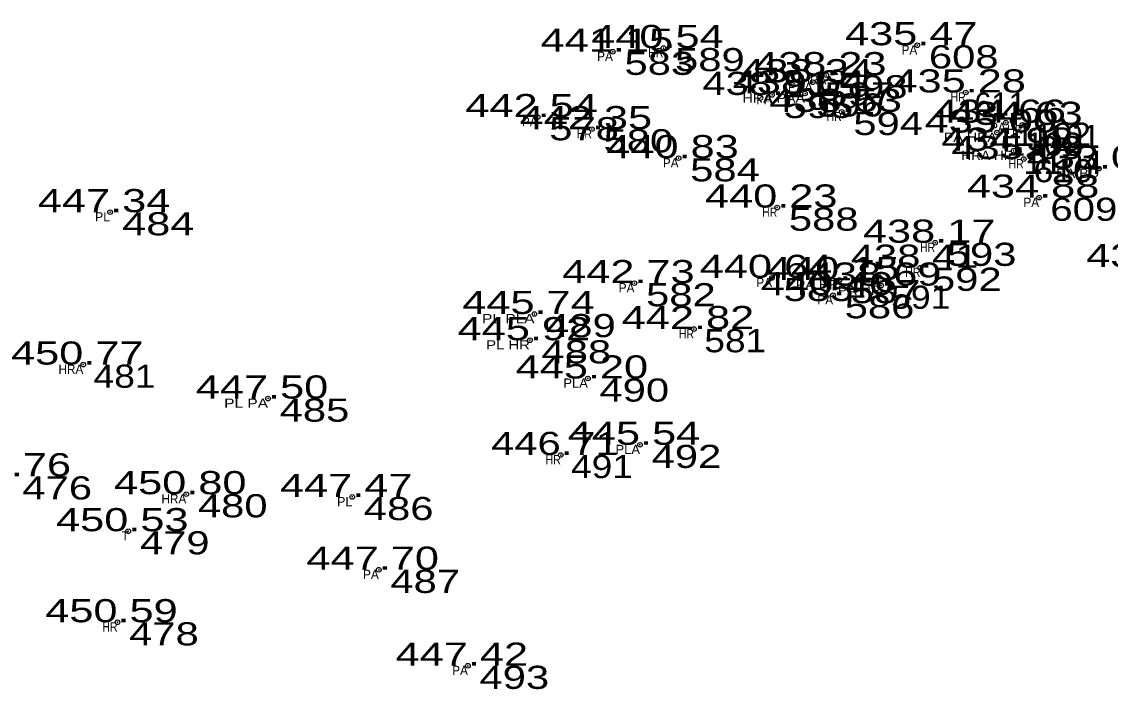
# Model space of a CAD drawing. Extents: x -639390 to -639074, y -1138747 to -1138358.
# Drawn here: x -639129.77 to -639094.48, y -1138747.34 to -1138725.71 of the extents above; entities that cross this region are included whole.
import ezdxf
from ezdxf.enums import TextEntityAlignment as Align

# ---------------------------------------------------------------- set-up
doc = ezdxf.new("R2010")
doc.units = 0
doc.header["$LTSCALE"] = 0.3
doc.header["$PDMODE"] = 32
doc.header["$PDSIZE"] = 0.15
for name, color, linetype in [('11', 7, 'Continuous'), ('12', 7, 'Continuous'), ('13', 7, 'Continuous'), ('57', 7, 'Continuous')]:
    doc.layers.add(name, color=color, linetype=linetype)

msp = doc.modelspace()

# ---------------------------------------------------------------- linework, layer by layer
at = {"layer": '11'}
for p in [(-639100.74, -1138726.47), (-639110.61, -1138726.68), (-639108.97, -1138726.56), (-639103.69, -1138727.44), (-639104.13, -1138727.67), (-639105.45, -1138728.08), (-639104.38, -1138728.03), (-639099.17, -1138728), (-639113.05, -1138728.8), (-639103.19, -1138728.63), (-639111.29, -1138729.19), (-639097.87, -1138728.98), (-639097.33, -1138729.05), (-639098.16, -1138729.3), (-639097.62, -1138729.89), (-639108.48, -1138730.13), (-639097.29, -1138730.16), (-639094.85, -1138730.47), (-639096.79, -1138731.41), (-639105.28, -1138731.73), (-639126.91, -1138731.88), (-639100.16, -1138732.87), (-639100.64, -1138733.68), (-639109.91, -1138734.18), (-639105.45, -1138734.01), (-639103.27, -1138734.08), (-639103.47, -1138734.57), (-639101.91, -1138734.26), (-639113.15, -1138735.18), (-639107.98, -1138735.67), (-639113.3, -1138736.03), (-639127.78, -1138736.82), (-639111.42, -1138737.27), (-639121.79, -1138737.92), (-639109.73, -1138739.42), (-639112.3, -1138739.75), (-639124.44, -1138741.02), (-639119.06, -1138741.11), (-639126.32, -1138742.22), (-639118.2, -1138743.47), (-639126.67, -1138745.17), (-639115.31, -1138746.58)]:
    msp.add_point(p, dxfattribs=at)

# ---------------------------------------------------------------- texts
at = {"layer": '12'}
for s, width, p in [('441.15 ', 1.4, (-639110.61, -1138726.68)), ('440.54 ', 1.4, (-639108.97, -1138726.56)), ('435.47 ', 1.4, (-639100.74, -1138726.47)), ('438.23 ', 1.4, (-639103.69, -1138727.44)), ('438.34 ', 1.4, (-639104.13, -1138727.67)), ('438.91 ', 1.35, (-639105.449, -1138728.08)), ('438.64 ', 1.4, (-639104.38, -1138728.03)), ('435.28 ', 1.4, (-639099.17, -1138728)), ('442.54 ', 1.4, (-639113.05, -1138728.8)), ('438.53 ', 1.4, (-639103.19, -1138728.63)), ('442.35 ', 1.4, (-639111.29, -1138729.19)), ('434.66 ', 1.4, (-639097.869, -1138728.98)), ('434.63 ', 1.4, (-639097.33, -1138729.05)), ('435.00 ', 1.4, (-639098.16, -1138729.3)), ('434.98 ', 1.4, (-639097.62, -1138729.89)), ('440.83 ', 1.4, (-639108.48, -1138730.13)), ('435.09 ', 1.4, (-639097.29, -1138730.16)), ('433.09 ', 1.4, (-639094.85, -1138730.47)), ('440.23 ', 1.4, (-639105.28, -1138731.73)), ('434.88 ', 1.4, (-639096.79, -1138731.41)), ('447.34 ', 1.4, (-639126.91, -1138731.88)), ('438.17 ', 1.4, (-639100.16, -1138732.87)), ('438.41 ', 1.35, (-639100.639, -1138733.68)), ('434.18 ', 1.4, (-639092.92, -1138733.66)), ('442.73 ', 1.4, (-639109.91, -1138734.18)), ('440.64 ', 1.4, (-639105.45, -1138734.01)), ('440.15 ', 1.4, (-639103.27, -1138734.08)), ('440.40 ', 1.4, (-639103.47, -1138734.57)), ('438.69 ', 1.4, (-639101.91, -1138734.26)), ('445.74 ', 1.4, (-639113.15, -1138735.18)), ('442.82 ', 1.4, (-639107.98, -1138735.67)), ('445.92 ', 1.4, (-639113.3, -1138736.03)), ('450.77 ', 1.4, (-639127.78, -1138736.82)), ('445.20 ', 1.4, (-639111.42, -1138737.27)), ('447.50 ', 1.4, (-639121.79, -1138737.92)), ('445.54 ', 1.4, (-639109.73, -1138739.42)), ('446.71 ', 1.35, (-639112.299, -1138739.75)), ('450.76 ', 1.4, (-639130.129, -1138740.44)), ('450.80 ', 1.4, (-639124.44, -1138741.02)), ('447.47 ', 1.4, (-639119.06, -1138741.11)), ('450.53 ', 1.4, (-639126.32, -1138742.22)), ('447.70 ', 1.4, (-639118.2, -1138743.47)), ('450.59 ', 1.4, (-639126.67, -1138745.17)), ('447.42 ', 1.4, (-639115.31, -1138746.58))]:
    msp.add_text(s, height=0.75, dxfattribs=dict(at, width=width)).set_placement(p, align=Align.CENTER)
at = {"layer": '13'}
for s, width, p in [(' 583', 1.35, (-639110.61, -1138727.43)), (' 589', 1.35, (-639108.97, -1138727.31)), (' 608', 1.35, (-639100.74, -1138727.22)), (' 598', 1.35, (-639103.69, -1138728.19)), (' 597', 1.35, (-639104.13, -1138728.42)), (' 595', 1.35, (-639105.45, -1138728.83)), (' 596', 1.3, (-639104.38, -1138728.78)), (' 578', 1.35, (-639113.05, -1138729.55)), (' 594', 1.35, (-639103.19, -1138729.38)), (' 580', 1.35, (-639111.29, -1138729.94)), (' 1102', 1.1, (-639097.87, -1138729.73)), (' 1103', 1.1, (-639098.16, -1138730.05)), (' 1104', 1.15, (-639097.62, -1138730.64)), (' 584', 1.35, (-639108.48, -1138730.88)), (' 610', 1.15, (-639097.29, -1138730.91)), (' 609', 1.3, (-639096.79, -1138732.16)), (' 484', 1.4, (-639126.91, -1138732.63)), (' 588', 1.35, (-639105.28, -1138732.48)), (' 593', 1.35, (-639100.16, -1138733.62)), (' 592', 1.35, (-639100.64, -1138734.43)), (' 585', 1.35, (-639105.45, -1138734.76)), (' 587', 1.35, (-639103.27, -1138734.83)), (' 582', 1.35, (-639109.91, -1138734.93)), (' 591', 1.15, (-639101.91, -1138735.01)), (' 586', 1.35, (-639103.47, -1138735.32)), (' 489', 1.35, (-639113.15, -1138735.93)), (' 581', 1.2, (-639107.98, -1138736.42)), (' 488', 1.35, (-639113.3, -1138736.78)), (' 481', 1.2, (-639127.78, -1138737.57)), (' 490', 1.35, (-639111.42, -1138738.02)), (' 485', 1.35, (-639121.79, -1138738.67)), (' 492', 1.35, (-639109.73, -1138740.17)), (' 491', 1.2, (-639112.3, -1138740.5)), (' 476', 1.35, (-639130.13, -1138741.19)), (' 480', 1.35, (-639124.44, -1138741.77)), (' 486', 1.35, (-639119.06, -1138741.86)), (' 479', 1.35, (-639126.32, -1138742.97)), (' 487', 1.35, (-639118.2, -1138744.22)), (' 478', 1.35, (-639126.67, -1138745.92)), (' 493', 1.35, (-639115.31, -1138747.33))]:
    msp.add_text(s, height=0.75, dxfattribs=dict(at, width=width)).set_placement(p)
for s, p in [(' 611', (-639099.17, -1138728.75)), (' 1101', (-639097.33, -1138729.8))]:
    msp.add_text(s, height=0.75, dxfattribs=at).set_placement(p)
at = {"layer": '57'}
for s, width, p in [('PA', 0.95, (-639110.61, -1138726.98)), ('HR', 0.85, (-639108.969, -1138726.86)), ('PA', 0.95, (-639100.74, -1138726.77)), ('HRA', 0.95, (-639103.69, -1138727.74)), ('HRA PAA', 1.15, (-639104.38, -1138728.33)), ('PA', 0.95, (-639105.45, -1138728.38)), ('HR', 0.85, (-639099.169, -1138728.3)), ('PA', 0.95, (-639113.05, -1138729.1)), ('HR', 0.85, (-639103.189, -1138728.93)), ('HR', 0.85, (-639111.289, -1138729.49)), ('PA', 0.95, (-639097.87, -1138729.28)), ('HR', 0.85, (-639097.329, -1138729.35)), ('PA HRA', 1.15, (-639098.16, -1138729.6)), ('HRA HR', 1.1, (-639097.619, -1138730.19)), ('PA', 0.95, (-639108.48, -1138730.43)), ('HR', 0.85, (-639097.289, -1138730.46)), ('PA BD', 1.15, (-639094.85, -1138730.77)), ('PA', 0.95, (-639096.79, -1138731.71)), ('HR', 0.85, (-639105.279, -1138732.03)), ('HR', 0.85, (-639100.159, -1138733.17)), ('HR', 0.85, (-639100.639, -1138733.98)), ('PA', 0.95, (-639105.45, -1138734.31)), ('PA HR', 1.15, (-639103.269, -1138734.38)), ('PA', 0.95, (-639109.91, -1138734.48)), ('PA HR', 1.15, (-639101.909, -1138734.56)), ('PA', 0.95, (-639103.47, -1138734.87)), ('PL PLA', 1.25, (-639113.15, -1138735.48)), ('HR', 0.85, (-639107.979, -1138735.97)), ('PL HR', 1.2, (-639113.299, -1138736.33)), ('HRA', 0.95, (-639127.78, -1138737.12)), ('PLA', 1.05, (-639111.42, -1138737.57)), ('PL PA', 1.25, (-639121.79, -1138738.22)), ('PLA', 1.05, (-639109.73, -1138739.72)), ('HR', 0.85, (-639112.299, -1138740.05)), ('HRA', 0.95, (-639124.44, -1138741.32)), ('T', 0.85, (-639126.32, -1138742.52)), ('PA', 0.95, (-639118.2, -1138743.77)), ('HR', 0.85, (-639126.669, -1138745.47)), ('PA', 0.95, (-639115.31, -1138746.88))]:
    msp.add_text(s, height=0.3, dxfattribs=dict(at, width=width)).set_placement(p, align=Align.RIGHT)
for s, p in [('PAA', (-639104.13, -1138727.97)), ('PL', (-639126.909, -1138732.18)), ('PL', (-639119.059, -1138741.41))]:
    msp.add_text(s, height=0.3, dxfattribs=at).set_placement(p, align=Align.RIGHT)

doc.saveas('drawing.dxf')
